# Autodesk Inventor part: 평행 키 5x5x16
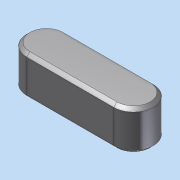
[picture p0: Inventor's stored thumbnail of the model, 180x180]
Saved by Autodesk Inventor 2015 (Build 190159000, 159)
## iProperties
Created: 2026-02
Part Number: 평행 키 5x5x16
Material: 일반
Document SubType Name: Modeling
Designer: Administrator
Density: 1 g/cm^3
Appearance: 기본값
Author: Administrator
Author: jhkim
Description: 키 및 해당 키홈
Creation Date: 2026-01-30
Sending System: Autodesk Inventor 2026
Preprocessor: ST-DEVELOPER v20.1
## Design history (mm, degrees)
node "평행 키 5x5x161"
body "Solid1"
node "기준1"
